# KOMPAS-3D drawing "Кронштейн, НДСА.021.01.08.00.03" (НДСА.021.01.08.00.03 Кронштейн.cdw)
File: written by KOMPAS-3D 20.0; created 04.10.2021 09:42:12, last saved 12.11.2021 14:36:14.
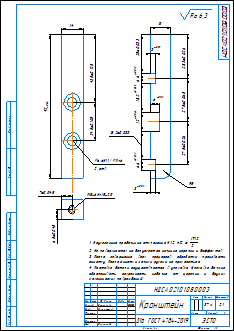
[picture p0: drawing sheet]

Sheet 1: A3, portrait

Document properties: Полное имя файла: C:\Users\korychko\Desktop\PLM\НДСА.021.01.08.00.03 Кронштейн.cdw; Автор: adminzsc; Параметр неуказанной шероховатости: Ra 6,3; PLM_CDWXDTO: <item xmlns="http://appius.ru/pdm" xmlns:xs="http://www.w3.org/2001/XMLSchema" xmlns:xsi="http://www.w3.org/2001/XMLSchema-instance" xsi:type="item">  <element xmlns:d2p1="http://v8.1c.ru/8.1/data/enterprise/current-config" xsi:type="d2p1:CatalogRef.aps_Элемен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; PDM_DOCXDTO: <item xmlns="http://appius.ru/pdm" xmlns:xs="http://www.w3.org/2001/XMLSchema" xmlns:xsi="http://www.w3.org/2001/XMLSchema-instance" xsi:type="item">  <element xmlns:d2p1="http://v8.1c.ru/8.1/data/enterprise/current-config" xsi:type="d2p1:CatalogRef.aps_Элемен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; PDM_ITEMXDTO: <item xmlns="http://appius.ru/pdm" xmlns:xs="http://www.w3.org/2001/XMLSchema" xmlns:xsi="http://www.w3.org/2001/XMLSchema-instance" xsi:type="item">  <element xmlns:d2p1="http://v8.1c.ru/8.1/data/enterprise/current-config" xsi:type="d2p1:CatalogRef.aps_Элемен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; Масса: 0.0369967; PDM_DRAWINGXDTO: <item xmlns="http://appius.ru/pdm" xmlns:xs="http://www.w3.org/2001/XMLSchema" xmlns:xsi="http://www.w3.org/2001/XMLSchema-instance" xsi:type="item">  <element xmlns:d2p1="http://v8.1c.ru/8.1/data/enterprise/current-config" xsi:type="d2p1:CatalogRef.aps_Элемен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

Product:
- Part/product: Кронштейн  | designation НДСА.021.01.08.00.03
    Материал: Д16  ГОСТ 4784-2019 (density 2800 kg/m3)
    Масса: 0.0369967
    additional columns: <item xmlns="http://appius.ru/pdm" xmlns:xs="http://www.w3.org/2001/XMLSchema" x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; <item xmlns="http://appius.ru/pdm" xmlns:xs="http://www.w3.org/2001/XMLSchema" x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; <item xmlns="http://appius.ru/pdm" xmlns:xs="http://www.w3.org/2001/XMLSchema" x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
    source file: НДСА.021.01.08.00.03 Кронштейн.cdw

Title block, sheet 1: Наименование: Кронштейн; designation: НДСА.021.01.08.00.03; Материал: Д16  ГОСТ 4784-2019; Масса: 37 г; Количество листов документа: 1; organisation: ЭСТО; Форматы листов документа: A3; stored path: C:\Users\vasilyeva\Desktop\PM_APPIUS\НДСА.021.01.08.00.03 Кронштейн.cdw; Разработал: Васильева; Проверил: Горностаев; Утвердил: Белецкий; Разработал, date: 04.10.2021

Views: Вид 1, Сзади, Проекционный вид 2, Проекционный вид 4
Referenced files in C:\Users\vasilyeva\Desktop\PM_APPIUS\: НДСА.021.01.08.00.03 Кронштейн.m3d
Referenced files in C:\Users\korychko\Desktop\PLM\: НДСА.021.01.08.00.03 Кронштейн.m3d
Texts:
  JS12
  JS9
  JS11
  Ra 6,3
  НДСА.021.01.08.00.03 Кронштейн
Dimensions and other numbers on the sheet: 14; 43,5±0,125; 24,5±0,105; 2 отв.; 92; 28,3±0,026; 13; 5; 6,6; 18,2±0,033; 12; 25±0,033; 27,5±0,026; 6; 3; 7±0,045; 6,5±0,045; 2:1; 1; 37 г; 04.10.2021

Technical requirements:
  Неуказанные предельные отклонения H12, h12,    IT12 2 .
  На поверхностях не допускается наличие царапин и деффектов.
  После завершения всех процессов обработки произвести
  очистку. После очистки голыми руками не прикосаться.
  Поставка детали осуществляется в упаковке. Упаковка должна
  обеспечивать сохранность изделия от царапин и других
  механических повреждений.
